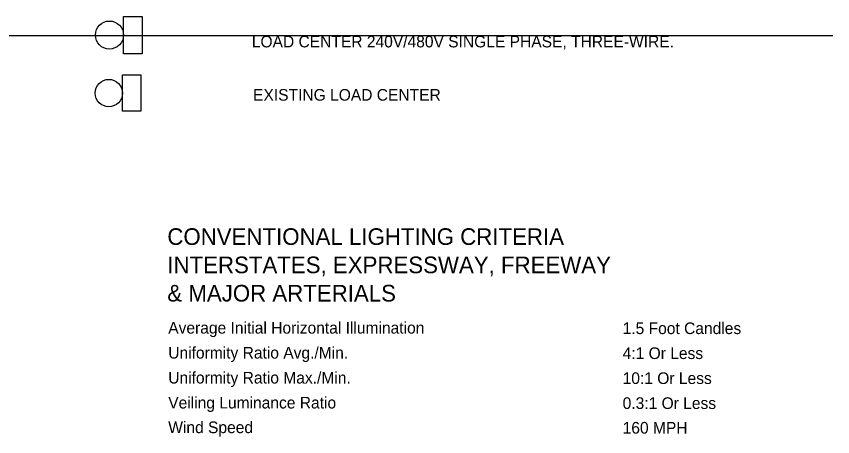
# Model space of a CAD drawing. Extents: x -9.1 to 15.2, y -0.9 to 9.2.
# Drawn here: x 9.703 to 14.612, y 6.364 to 8.889 of the extents above; entities that cross this region are included whole.
import ezdxf

# ---------------------------------------------------------------- set-up
doc = ezdxf.new("R2010")
doc.units = 0
for name, color, linetype in [('ActivePointCell_dp', 7, 'Continuous'), ('LoadCenter', 7, 'Continuous'), ('LoadCenter_ep', 7, 'Continuous'), ('TextLabel', 7, 'Continuous'), ('TextMisc', 7, 'Continuous'), ('TextNotes', 7, 'Continuous')]:
    doc.layers.add(name, color=color, linetype=linetype)

msp = doc.modelspace()

# ---------------------------------------------------------------- linework, layer by layer
at = {"layer": 'ActivePointCell_dp'}
msp.add_line((14.612, 8.7727), (0.2875, 8.7727), dxfattribs=at)
at = {"layer": 'LoadCenter'}
for p, q in [((10.3476, 8.6644), (10.3476, 8.8892)), ((10.3476, 8.8892), (10.4601, 8.8892)), ((10.4601, 8.8892), (10.4601, 8.6644)), ((10.4601, 8.6644), (10.3476, 8.6644))]:
    msp.add_line(p, q, dxfattribs=at)
msp.add_circle((10.2633, 8.7768), 0.0843, dxfattribs=at)
at = {"layer": 'LoadCenter_ep'}
for p, q in [((10.3421, 8.3187), (10.3421, 8.538)), ((10.3421, 8.538), (10.4518, 8.538)), ((10.4518, 8.538), (10.4518, 8.3187)), ((10.4518, 8.3187), (10.3421, 8.3187))]:
    msp.add_line(p, q, dxfattribs=at)
msp.add_circle((10.2599, 8.4283), 0.0822, dxfattribs=at)

# ---------------------------------------------------------------- texts
at = {"layer": 'TextLabel'}
for s, p in [('CONVENTIONAL LIGHTING CRITERIA', (10.6114, 7.5158)), ('INTERSTATES, EXPRESSWAY, FREEWAY', (10.6114, 7.3458)), ('& MAJOR ARTERIALS', (10.6114, 7.1758))]:
    msp.add_text(s, height=0.1, dxfattribs=at).set_placement(p)
at = {"layer": 'TextMisc'}
for s, p in [('LOAD CENTER 240V/480V SINGLE PHASE, THREE-WIRE.', (11.1193, 8.7027)), ('EXISTING LOAD CENTER', (11.127, 8.3825))]:
    msp.add_text(s, height=0.07, rotation=360, dxfattribs=at).set_placement(p)
at = {"layer": 'TextNotes'}
for s, p in [('Average Initial Horizontal Illumination', (10.6168, 6.983)), ('1.5 Foot Candles', (13.3491, 6.9801)), ('Uniformity Ratio Avg./Min.', (10.6168, 6.833)), ('4:1 Or Less', (13.3491, 6.8301)), ('Uniformity Ratio Max./Min.', (10.6168, 6.683)), ('10:1 Or Less', (13.3491, 6.6801)), ('Veiling Luminance Ratio', (10.6168, 6.533)), ('0.3:1 Or Less', (13.3491, 6.5301)), ('Wind Speed', (10.6168, 6.3848)), ('160 MPH', (13.3491, 6.382))]:
    msp.add_text(s, height=0.07, dxfattribs=at).set_placement(p)

doc.saveas('drawing.dxf')
